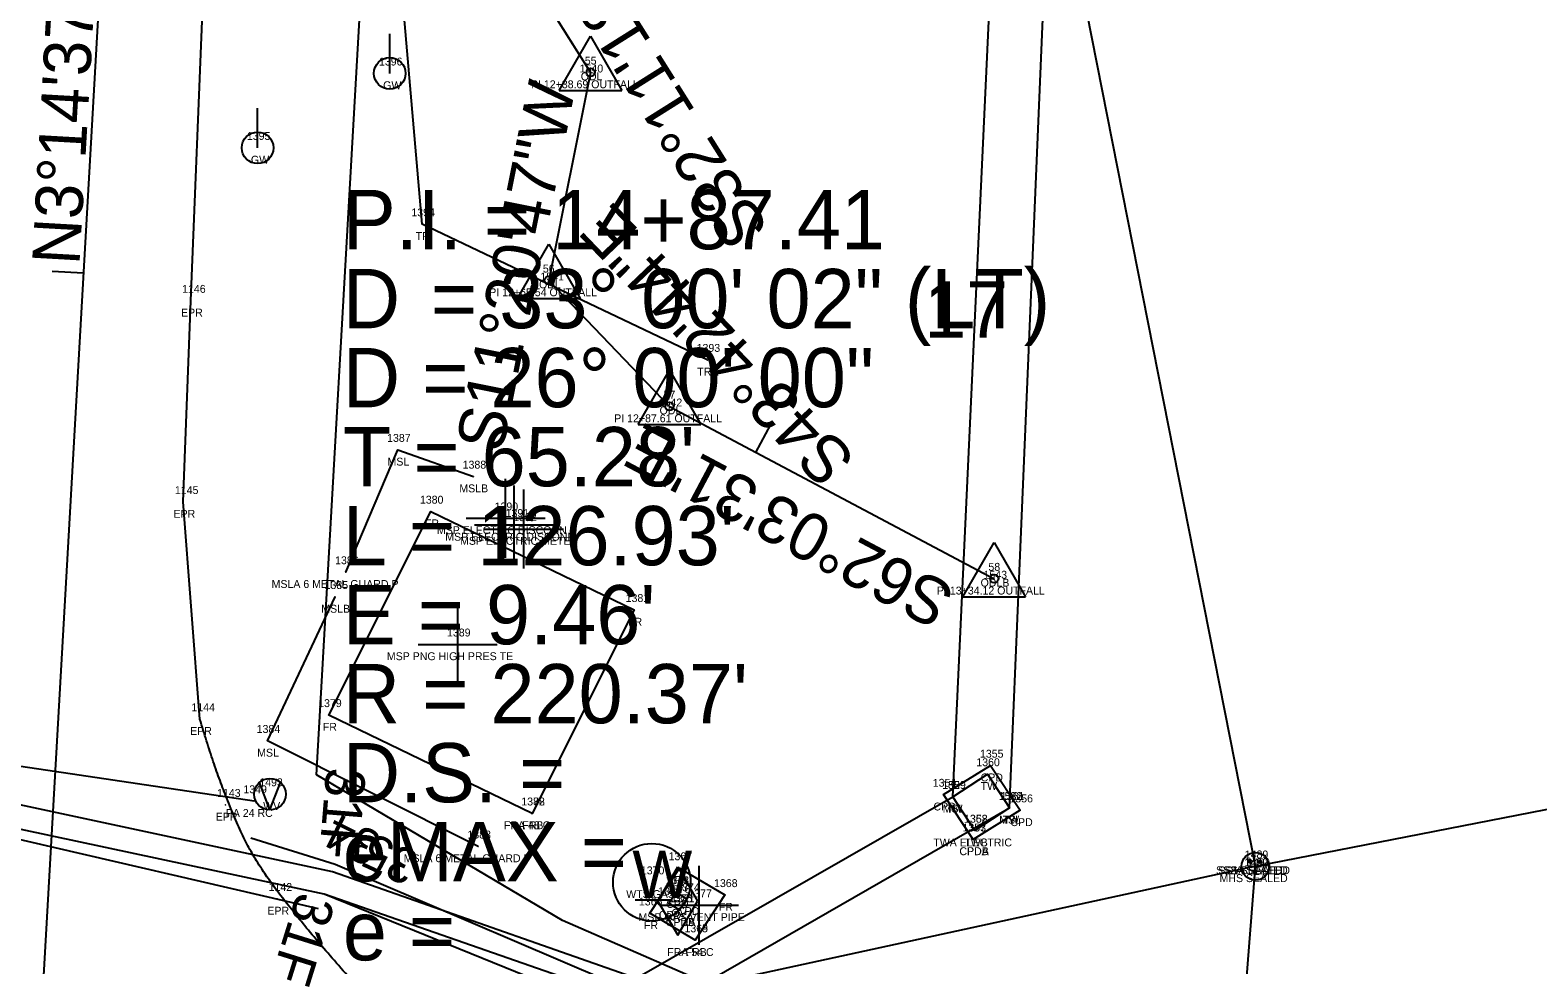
# Model space of a CAD drawing. Extents: x 1812113 to 1819860, y 1177395 to 1181185.
# Drawn here: x 1813662.4 to 1813853.2, y 1178765.4 to 1178883.7 of the extents above; entities that cross this region are included whole.
import ezdxf

# ---------------------------------------------------------------- set-up
doc = ezdxf.new("R2010")
doc.units = 0
for name, color, linetype in [('RD_EX_Conc', 7, 'Continuous'), ('RD_EX_Conc_txCode', 7, 'Continuous'), ('RD_EX_DR_Inlet', 7, 'Continuous'), ('RD_EX_DR_Pipe', 7, 'Continuous'), ('RD_EX_DR_Pipe_txCode', 7, 'Continuous'), ('RD_EX_DV_TX_Prop', 7, 'Continuous'), ('RD_EX_Fence_Other', 7, 'Continuous'), ('RD_EX_Fence_Other_txCode', 7, 'Continuous'), ('RD_EX_H2O', 7, 'Continuous'), ('RD_EX_H2O_txCode', 7, 'Continuous'), ('RD_EX_Misc', 7, 'Continuous'), ('RD_EX_Misc_txCode', 7, 'Continuous'), ('RD_EX_Road', 7, 'Continuous'), ('RD_EX_Road_txCode', 7, 'Continuous'), ('RD_EX_RW', 7, 'Continuous'), ('RD_EX_UT', 7, 'Continuous'), ('RD_EX_UT_txCode', 7, 'Continuous'), ('RD_EX_VEG', 7, 'Continuous'), ('RD_EX_VEG_txCode', 7, 'Continuous'), ('RD_HC_CL', 7, 'Continuous'), ('RD_HC_Data', 7, 'Continuous'), ('RD_HC_Data_Tic', 7, 'Continuous'), ('RD_HC_TX_StaOther', 7, 'Continuous'), ('RD_HC_txCode', 7, 'Continuous'), ('RD_PD_ALT1_TnTmp', 7, 'Continuous'), ('RD_PD_ALT3_LnLine', 7, 'Continuous'), ('RD_PD_ALT4_LnLine', 7, 'Continuous'), ('RD_PD_CstnLmt', 7, 'Continuous'), ('RD_SMD_Locator', 7, 'Continuous')]:
    doc.layers.add(name, color=color, linetype=linetype)

msp = doc.modelspace()

# ---------------------------------------------------------------- linework, layer by layer
at = {"layer": 'RD_EX_Conc'}
for points in [[(1813781.73, 1178781.31), (1813777.98, 1178786.97), (1813783.94, 1178790.65), (1813787.7, 1178784.99), (1813781.73, 1178781.31)], [(1813744.59, 1178772.35), (1813743.23, 1178773.25), (1813744.16, 1178774.64), (1813745.52, 1178773.74), (1813744.59, 1178772.35)]]:
    msp.add_lwpolyline(points, dxfattribs=at)
at = {"layer": 'RD_EX_DR_Inlet'}
for centre, radius in [((1813817.45, 1178777.9), 1.75), ((1813816.78, 1178778.53), 0.175), ((1813817.36, 1178777.24), 0.175), ((1813818.01, 1178778.46), 0.175)]:
    msp.add_circle(centre, radius, dxfattribs=at)
at = {"layer": 'RD_EX_DR_Pipe'}
msp.add_line((1813690.77, 1178786.15), (1813637.71, 1178794.06), dxfattribs=at)
at = {"layer": 'RD_EX_Fence_Other'}
for points in [[(1813725.93, 1178784.6), (1813700.22, 1178797.05), (1813713.13, 1178822.8), (1813738.84, 1178810.35), (1813725.93, 1178784.6)], [(1813746.59, 1178768.55), (1813740.84, 1178771.95), (1813744.58, 1178777.67), (1813750.33, 1178774.27), (1813746.59, 1178768.55)]]:
    msp.add_lwpolyline(points, dxfattribs=at)
at = {"layer": 'RD_EX_H2O'}
msp.add_lwpolyline([(1813697.92, 1178915.85), (1813709.32, 1178901.76), (1813721.45, 1178897.26), (1813733.34, 1178878.37), (1813728.06, 1178852.05), (1813743.31, 1178836.1), (1813784.4, 1178814.3)], dxfattribs=at)
at = {"layer": 'RD_EX_Misc'}
for p, q in [((1813722.59, 1178816.94), (1813722.59, 1178826.94)), ((1813723.66, 1178816.11), (1813723.66, 1178826.11)), ((1813724.9, 1178815.59), (1813724.9, 1178825.59)), ((1813717.59, 1178821.94), (1813727.59, 1178821.94)), ((1813718.66, 1178821.11), (1813728.66, 1178821.11)), ((1813719.9, 1178820.59), (1813729.9, 1178820.59)), ((1813716.53, 1178800.99), (1813716.53, 1178810.99)), ((1813711.53, 1178805.99), (1813721.53, 1178805.99)), ((1813747.06, 1178767.97), (1813747.06, 1178777.97)), ((1813742.06, 1178772.97), (1813752.06, 1178772.97))]:
    msp.add_line(p, q, dxfattribs=at)
for points in [[(1813405.71, 1178572.74), (1813779.17, 1178786.7), (1813799.35, 1179222.21)], [(1813408.47, 1178567.92), (1813786.33, 1178785.29), (1813804.76, 1179221.83)], [(1813702.39, 1178815.13), (1813708.94, 1178830.62), (1813718.51, 1178827.23)], [(1813719.11, 1178780.42), (1813692.45, 1178793.78), (1813701.04, 1178812)]]:
    msp.add_lwpolyline(points, dxfattribs=at)
at = {"layer": 'RD_EX_Road'}
for p, q in [((1813682.76, 1178849.48), (1813684.82, 1178900.28)), ((1813681.81, 1178824.01), (1813682.76, 1178849.48)), ((1813683.91, 1178796.53), (1813681.81, 1178824.01))]:
    msp.add_line(p, q, dxfattribs=at)
msp.add_open_spline([(1813706.04, 1178760.25), (1813693.68, 1178773.78), (1813687.15, 1178785.68), (1813683.91, 1178796.53)], degree=2, dxfattribs=at)
at = {"layer": 'RD_EX_RW'}
for p, q in [((1813698.67, 1178789.48), (1813713.48, 1179050.77)), ((1813729.8, 1178771.04), (1813698.67, 1178789.48)), ((1813768.43, 1178754.21), (1813729.8, 1178771.04))]:
    msp.add_line(p, q, dxfattribs=at)
at = {"layer": 'RD_EX_UT'}
for p, q in [((1813707.94, 1178878.25), (1813707.94, 1178883.25)), ((1813691.21, 1178868.83), (1813691.21, 1178873.83)), ((1813692.78, 1178785.04), (1813691.47, 1178788.52)), ((1813692.78, 1178785.04), (1813694.1, 1178788.49)), ((1813741.86, 1178773.5), (1813744.36, 1178777.83)), ((1813744.36, 1178777.83), (1813746.86, 1178773.5)), ((1813738.96, 1178773.67), (1813743.59, 1178773.67)), ((1813741.86, 1178773.5), (1813744.36, 1178769.17)), ((1813744.36, 1178769.17), (1813746.86, 1178773.5))]:
    msp.add_line(p, q, dxfattribs=at)
for points in [[(1813817.45, 1178777.9), (1813754.12, 1179098.9), (1813749.26, 1179176.64)], [(1814122.48, 1178351.31), (1814099.73, 1178371.68), (1813807.05, 1178645.14), (1813817.45, 1178777.9), (1813883.81, 1178790.87)], [(1813781.95, 1178782.42), (1813779.17, 1178786.7), (1813783.55, 1178789.57), (1813786.33, 1178785.29), (1813781.95, 1178782.42)], [(1813817.45, 1178777.9), (1813490.2, 1178706.76), (1813294.33, 1178669.42)]]:
    msp.add_lwpolyline(points, dxfattribs=at)
for centre, radius in [((1813707.94, 1178878.25), 2), ((1813691.21, 1178868.83), 2), ((1813692.78, 1178787.03), 2), ((1813741.09, 1178775.88), 4.91)]:
    msp.add_circle(centre, radius, dxfattribs=at)
at = {"layer": 'RD_EX_VEG'}
msp.add_lwpolyline([(1813748.11, 1178842.01), (1813712.02, 1178859.16), (1813709.48, 1178888.95), (1813708.93, 1178949.18), (1813715.24, 1179043.86)], dxfattribs=at)
at = {"layer": 'RD_HC_CL'}
for p, q in [((1813663.56, 1178753.12), (1813680.53, 1179052.64)), ((1813721.45, 1178897.26), (1813733.34, 1178878.37)), ((1813733.34, 1178878.37), (1813728.06, 1178852.05)), ((1813728.06, 1178852.05), (1813743.31, 1178836.1)), ((1813743.31, 1178836.1), (1813784.4, 1178814.3))]:
    msp.add_line(p, q, dxfattribs=at)
at = {"layer": 'RD_HC_Data'}
for p, q in [((1813729.37, 1178876.08), (1813733.34, 1178882.96)), ((1813733.34, 1178882.96), (1813737.31, 1178876.08)), ((1813729.37, 1178876.08), (1813737.31, 1178876.08)), ((1813724.09, 1178849.75), (1813728.06, 1178856.63)), ((1813728.06, 1178856.63), (1813732.03, 1178849.75)), ((1813724.09, 1178849.75), (1813732.03, 1178849.75)), ((1813739.34, 1178833.8), (1813743.31, 1178840.68)), ((1813743.31, 1178840.68), (1813747.28, 1178833.8)), ((1813739.34, 1178833.8), (1813747.28, 1178833.8)), ((1813780.43, 1178812.01), (1813784.4, 1178818.89)), ((1813784.4, 1178818.89), (1813788.37, 1178812.01)), ((1813780.43, 1178812.01), (1813788.37, 1178812.01))]:
    msp.add_line(p, q, dxfattribs=at)
for centre in [(1813733.34, 1178878.37), (1813728.06, 1178852.05), (1813743.31, 1178836.1), (1813784.4, 1178814.3)]:
    msp.add_circle(centre, 0.529, dxfattribs=at)
at = {"layer": 'RD_HC_Data_Tic'}
for p, q in [((1813669.21, 1178852.96), (1813665.22, 1178853.18)), ((1813754.26, 1178830.29), (1813756.13, 1178833.82))]:
    msp.add_line(p, q, dxfattribs=at)
at = {"layer": 'RD_PD_ALT3_LnLine'}
for p, q in [((1813700.68, 1178777.2), (1813644.68, 1178789.17)), ((1813699.62, 1178774.39), (1813644.27, 1178786.2)), ((1813756.39, 1178757.69), (1813700.68, 1178777.2)), ((1813754.74, 1178755.19), (1813699.62, 1178774.39))]:
    msp.add_line(p, q, dxfattribs=at)
at = {"layer": 'RD_PD_ALT4_LnLine'}
for p, q in [((1813701.03, 1178778.14), (1813690.37, 1178781.45)), ((1813754.74, 1178755.19), (1813701.03, 1178778.14)), ((1813753.08, 1178752.69), (1813699.62, 1178774.39))]:
    msp.add_line(p, q, dxfattribs=at)
at = {"layer": 'RD_PD_CstnLmt'}
msp.add_line((1813698.92, 1178772.52), (1813644.14, 1178785.21), dxfattribs=at)
at = {"layer": 'RD_SMD_Locator'}
for centre in [(1813733.34, 1178878.37), (1813733.34, 1178878.37), (1813712.02, 1178859.16), (1813728.06, 1178852.05), (1813728.06, 1178852.05), (1813682.76, 1178849.48), (1813748.11, 1178842.01), (1813743.31, 1178836.1), (1813743.31, 1178836.1), (1813708.94, 1178830.62), (1813718.51, 1178827.23), (1813681.81, 1178824.01), (1813713.13, 1178822.8), (1813702.39, 1178815.13), (1813784.4, 1178814.3), (1813784.4, 1178814.3), (1813701.04, 1178812), (1813738.84, 1178810.35), (1813683.91, 1178796.53), (1813700.22, 1178797.05), (1813692.45, 1178793.78), (1813783.55, 1178789.57), (1813783.94, 1178790.65), (1813777.98, 1178786.97), (1813687.15, 1178785.68), (1813690.77, 1178786.15), (1813779.17, 1178786.7), (1813779.17, 1178786.7), (1813786.33, 1178785.29), (1813786.33, 1178785.29), (1813787.7, 1178784.99), (1813725.93, 1178784.6), (1813725.93, 1178784.6), (1813781.73, 1178781.31), (1813781.73, 1178781.31), (1813781.95, 1178782.42), (1813781.95, 1178782.42), (1813719.11, 1178780.42), (1813744.58, 1178777.67), (1813817.45, 1178777.9), (1813817.45, 1178777.9), (1813817.45, 1178777.9), (1813693.68, 1178773.78), (1813744.16, 1178774.64), (1813745.52, 1178773.74), (1813750.33, 1178774.27), (1813740.84, 1178771.95), (1813743.23, 1178773.25), (1813744.59, 1178772.35), (1813744.59, 1178772.35), (1813746.59, 1178768.55), (1813746.59, 1178768.55)]:
    msp.add_circle(centre, 0.001, dxfattribs=at)

# ---------------------------------------------------------------- texts
at = {"layer": 'RD_EX_Conc_txCode'}
for s, p in [('1355', (1813782.6, 1178791.65)), ('1354', (1813776.63, 1178787.97)), ('CPD', (1813782.69, 1178788.65)), ('1356', (1813786.33, 1178785.99)), ('CPD', (1813776.72, 1178784.97)), ('1353', (1813780.39, 1178782.31)), ('1357', (1813780.39, 1178782.31)), ('CPD', (1813786.45, 1178782.99)), ('CPDA', (1813779.99, 1178779.31)), ('CPDB', (1813780.01, 1178779.31)), ('1373', (1813742.82, 1178775.64)), ('1374', (1813744.18, 1178774.74)), ('1372', (1813741.89, 1178774.25)), ('CPD', (1813742.91, 1178772.64)), ('1375', (1813743.25, 1178773.35)), ('1371', (1813743.53, 1178773.35)), ('CPD', (1813741.98, 1178771.25)), ('CPD', (1813744.27, 1178771.74)), ('CPDA', (1813742.85, 1178770.35)), ('CPDB', (1813742.87, 1178770.35))]:
    msp.add_text(s, height=1, dxfattribs=at).set_placement(p)
at = {"layer": 'RD_EX_DR_Pipe_txCode'}
for s, p in [('1349', (1813689.42, 1178787.15)), ('PA 24 RC', (1813687.19, 1178784.15))]:
    msp.add_text(s, height=1, dxfattribs=at).set_placement(p)
at = {"layer": 'RD_EX_DV_TX_Prop'}
msp.add_text('17', height=7.14, dxfattribs=at).set_placement((1813775.55, 1178844.79))
at = {"layer": 'RD_EX_Fence_Other_txCode'}
for s, p in [('1380', (1813711.75, 1178823.8)), ('FR', (1813712.38, 1178820.8)), ('1381', (1813737.78, 1178811.35)), ('FR', (1813738.08, 1178808.35)), ('1379', (1813698.88, 1178798.05)), ('FR', (1813699.47, 1178795.05)), ('1378', (1813724.58, 1178785.6)), ('1382', (1813724.58, 1178785.6)), ('FRA 48 C', (1813722.38, 1178782.6)), ('FRB', (1813724.7, 1178782.6)), ('1367', (1813743.21, 1178778.67)), ('FR', (1813743.82, 1178775.67)), ('1368', (1813748.96, 1178775.27)), ('1366', (1813739.45, 1178772.95)), ('FR', (1813749.57, 1178772.27)), ('FR', (1813740.09, 1178769.95)), ('1365', (1813745.22, 1178769.55)), ('1369', (1813745.22, 1178769.55)), ('FRA 54 C', (1813743.04, 1178766.55)), ('FRB', (1813745.36, 1178766.55))]:
    msp.add_text(s, height=1, dxfattribs=at).set_placement(p)
at = {"layer": 'RD_EX_H2O_txCode'}
for s, p in [('1540', (1813731.96, 1178878.37)), ('ODL', (1813732.1, 1178877.37)), ('ODL', (1813726.82, 1178851.05)), ('1541', (1813727, 1178852.05)), ('1542', (1813741.96, 1178836.1)), ('ODL', (1813742.07, 1178835.1)), ('ODLB', (1813782.68, 1178813.3)), ('1543', (1813783.05, 1178814.3))]:
    msp.add_text(s, height=1, dxfattribs=at).set_placement(p)
at = {"layer": 'RD_EX_Misc_txCode'}
for s, p in [('1387', (1813707.6, 1178831.62)), ('MSL', (1813707.65, 1178828.62)), ('1388', (1813717.16, 1178828.23)), ('MSLB', (1813716.74, 1178825.23)), ('1390', (1813721.2, 1178822.94)), ('1391', (1813722.59, 1178822.11)), ('1392', (1813723.55, 1178821.59)), ('MSP ELECTRIC DISCONN', (1813713.9, 1178819.94)), ('MSP ELECTRIC DISCONN', (1813714.96, 1178819.11)), ('MSP ELECTRIC METER', (1813716.83, 1178818.59)), ('1386', (1813701.02, 1178816.13)), ('MSLA 6 METAL GUARD P', (1813692.99, 1178813.13)), ('1385', (1813699.69, 1178813)), ('MSLB', (1813699.27, 1178810)), ('1389', (1813715.18, 1178806.99)), ('MSP PNG HIGH PRES TE', (1813707.57, 1178803.99)), ('1384', (1813691.1, 1178794.78)), ('MSL', (1813691.16, 1178791.78)), ('1529', (1813777.83, 1178787.7)), ('1532', (1813784.98, 1178786.29)), ('MSL', (1813777.88, 1178784.7)), ('MSL', (1813785.04, 1178783.29)), ('1383', (1813717.76, 1178781.42)), ('MSLA 6 METAL GUARD P', (1813709.7, 1178778.42)), ('1377', (1813745.71, 1178773.97)), ('MSP GAS VENT PIPE', (1813739.4, 1178770.97))]:
    msp.add_text(s, height=1, dxfattribs=at).set_placement(p)
at = {"layer": 'RD_EX_Road_txCode'}
for s, p in [('1146', (1813681.67, 1178850.48)), ('EPR', (1813681.53, 1178847.48)), ('1145', (1813680.75, 1178825.01)), ('EPR', (1813680.58, 1178822.01)), ('1144', (1813682.85, 1178797.53)), ('EPR', (1813682.68, 1178794.53)), ('1143', (1813686.09, 1178786.68)), ('EPR', (1813685.92, 1178783.68)), ('1142', (1813692.61, 1178774.78)), ('EPR', (1813692.45, 1178771.78))]:
    msp.add_text(s, height=1, dxfattribs=at).set_placement(p)
at = {"layer": 'RD_EX_UT'}
msp.add_text('W', height=6, dxfattribs=at).set_placement((1813738.62, 1178773.88))
at = {"layer": 'RD_EX_UT_txCode'}
for s, p in [('1396', (1813706.57, 1178879.25)), ('GW', (1813707.1, 1178876.25)), ('1395', (1813689.86, 1178869.83)), ('GW', (1813690.37, 1178866.83)), ('1360', (1813782.14, 1178790.57)), ('1493', (1813691.43, 1178788.03)), ('1359', (1813777.83, 1178787.7)), ('TW', (1813782.69, 1178787.57)), ('1361', (1813785.24, 1178786.29)), ('WV', (1813691.92, 1178785.03)), ('TW', (1813778.32, 1178784.7)), ('1362', (1813780.58, 1178783.42)), ('1358', (1813780.6, 1178783.42)), ('TW', (1813785.47, 1178783.29)), ('TWA ELECTRIC', (1813776.7, 1178780.42)), ('TWB', (1813780.62, 1178780.42)), ('1489', (1813816.1, 1178778.9)), ('1370', (1813739.7, 1178776.88)), ('SS2A SEALED', (1813812.46, 1178776.9)), ('SS1A SEALED', (1813812.75, 1178776.9)), ('SS SEALED', (1813813.42, 1178776.9)), ('1490', (1813816.06, 1178777.9)), ('1492', (1813816.1, 1178777.9)), ('1491', (1813816.39, 1178777.9)), ('1376', (1813742.99, 1178774.5)), ('MHS SEALED', (1813812.91, 1178775.9)), ('WTS GAS', (1813737.85, 1178773.88)), ('GV', (1813743.57, 1178771.5))]:
    msp.add_text(s, height=1, dxfattribs=at).set_placement(p)
at = {"layer": 'RD_EX_VEG_txCode'}
for s, p in [('1394', (1813710.67, 1178860.16)), ('TR', (1813711.22, 1178857.16)), ('1393', (1813746.76, 1178843.01)), ('TRA', (1813746.83, 1178840.01))]:
    msp.add_text(s, height=1, dxfattribs=at).set_placement(p)
at = {"layer": 'RD_HC_Data'}
for s, rotation, p in [('S32%%d11\'18"E', 122.1883, (1813756.03, 1178858.6)), ('N3%%d14\'37"E', 86.7565, (1813668.67, 1178853.93)), ('S43%%d42\'44"E', 133.7122, (1813767.1, 1178829.56)), ('S62%%d03\'31"E', 152.0585, (1813779.76, 1178813.04))]:
    msp.add_text(s, height=6, rotation=rotation, dxfattribs=at).set_placement(p)
at = {"layer": 'RD_HC_TX_StaOther'}
for s, p in [('P.I. = 14+87.41', (1813702, 1178856)), ('    = 33%%d 00\' 02" (LT)', (1813702, 1178846)), ('D', (1813702, 1178846)), ('D = 26%%d 00\' 00"', (1813702, 1178836)), ("T = 65.28'", (1813702, 1178826)), ("L = 126.93'", (1813702, 1178816)), ("E = 9.46'", (1813702, 1178806)), ("R = 220.37'", (1813702, 1178796)), ('D.S. = ', (1813702, 1178786)), ('eMAX = ', (1813702, 1178776)), ('e = ', (1813702, 1178766))]:
    msp.add_text(s, height=7.5, dxfattribs=at).set_placement(p)
at = {"layer": 'RD_HC_txCode'}
for s, p in [('55', (1813732.61, 1178879.37)), ('PI 12+38.69 OUTFALL', (1813725.8, 1178876.37)), ('56', (1813727.3, 1178853.05)), ('PI 12+65.54 OUTFALL', (1813720.52, 1178850.05)), ('57', (1813742.58, 1178837.1)), ('PI 12+87.61 OUTFALL', (1813736.33, 1178834.1)), ('58', (1813783.67, 1178815.3)), ('PI 13+34.12 OUTFALL', (1813777.16, 1178812.3))]:
    msp.add_text(s, height=1, dxfattribs=at).set_placement(p)
at = {"layer": 'RD_PD_ALT1_TnTmp'}
msp.add_text('S11%%d20\'47"W', height=6, rotation=78.6536, dxfattribs=at).set_placement((1813722.16, 1178830.14))
at = {"layer": 'RD_PD_ALT3_LnLine'}
for s, height, rotation, p in [('34', 4.5, 153.6336, (1813707.22, 1178781.77)), ('31F', 5, 252.6361, (1813696.32, 1178774.86))]:
    msp.add_text(s, height=height, rotation=rotation, dxfattribs=at).set_placement(p)
at = {"layer": 'RD_PD_ALT4_LnLine'}
for s, height, rotation, p in [('31F', 5, 265.3366, (1813699.93, 1178790.49)), ('35', 4.5, 155.0998, (1813711.93, 1178779.41))]:
    msp.add_text(s, height=height, rotation=rotation, dxfattribs=at).set_placement(p)

doc.saveas('drawing.dxf')
